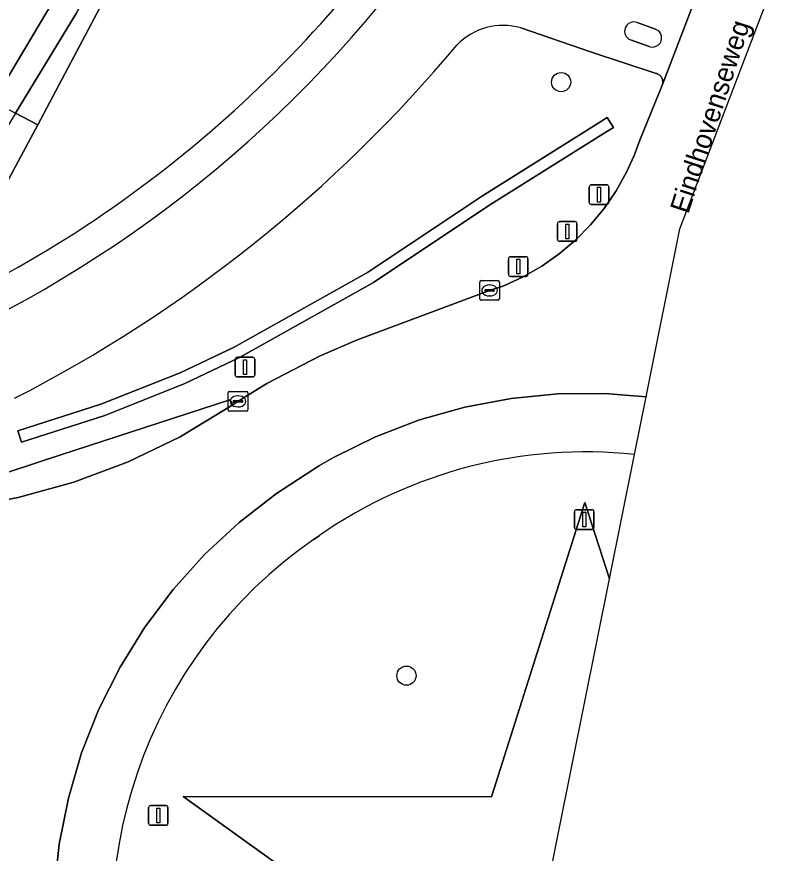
# Model space of a CAD drawing. Extents: x 161385 to 162589, y 388479 to 389756.
# Drawn here: x 162484.61 to 162522.82, y 388644.42 to 388686.96 of the extents above; entities that cross this region are included whole.
import ezdxf

# ---------------------------------------------------------------- set-up
doc = ezdxf.new("R2010")
doc.units = 0
for name, color, linetype in [('IMGEO_Afsluitpaal', 7, 'Continuous'), ('IMGEO_Berm_groen', 7, 'Continuous'), ('IMGEO_Boom', 7, 'Continuous'), ('IMGEO_Fietspad_gesloten', 7, 'Continuous'), ('IMGEO_Groenvoorziening', 7, 'Continuous'), ('IMGEO_Haag', 7, 'Continuous'), ('IMGEO_Kolk', 7, 'Continuous'), ('IMGEO_Lichtmast', 7, 'Continuous'), ('IMGEO_Oever', 7, 'Continuous'), ('IMGEO_Openbare_ruimte_label', 7, 'Continuous'), ('IMGEO_Rijbaan_lokaal_gesloten', 7, 'Continuous'), ('IMGEO_Rijbaan_regionaal_gesloten', 7, 'Continuous'), ('IMGEO_Verkeersbordpaal', 7, 'Continuous'), ('IMGEO_Verkeerseiland_open', 7, 'Continuous'), ('IMGEO_Voetpad_open', 7, 'Continuous'), ('IMGEO_Waterloop', 7, 'Continuous')]:
    doc.layers.add(name, color=color, linetype=linetype)

msp = doc.modelspace()

# ---------------------------------------------------------------- linework, layer by layer
at = {"layer": 'IMGEO_Afsluitpaal'}
for p, q in [((162513.826, 388678.412), (162514.616, 388678.412)), ((162514.616, 388678.412), (162513.826, 388678.412)), ((162513.726, 388677.512), (162513.726, 388678.312)), ((162513.726, 388678.312), (162513.726, 388677.512)), ((162514.716, 388678.312), (162514.716, 388677.512)), ((162514.716, 388677.512), (162514.716, 388678.312)), ((162514.616, 388677.412), (162513.826, 388677.412)), ((162513.826, 388677.412), (162514.616, 388677.412)), ((162512.108, 388675.642), (162512.108, 388676.442)), ((162512.108, 388676.442), (162512.108, 388675.642)), ((162512.208, 388676.542), (162512.998, 388676.542)), ((162512.998, 388676.542), (162512.208, 388676.542)), ((162513.098, 388676.442), (162513.098, 388675.642)), ((162513.098, 388675.642), (162513.098, 388676.442)), ((162512.998, 388675.542), (162512.208, 388675.542)), ((162512.208, 388675.542), (162512.998, 388675.542)), ((162509.615, 388673.854), (162509.615, 388674.654)), ((162509.615, 388674.654), (162509.615, 388673.854)), ((162509.715, 388674.754), (162510.505, 388674.754)), ((162510.505, 388674.754), (162509.715, 388674.754)), ((162510.605, 388674.654), (162510.605, 388673.854)), ((162510.605, 388673.854), (162510.605, 388674.654)), ((162510.505, 388673.754), (162509.715, 388673.754)), ((162509.715, 388673.754), (162510.505, 388673.754))]:
    msp.add_line(p, q, dxfattribs=at)
for points in [[(162514.146, 388678.287), (162514.296, 388678.287), (162514.296, 388677.537), (162514.146, 388677.537), (162514.146, 388678.287)], [(162512.528, 388676.417), (162512.678, 388676.417), (162512.678, 388675.667), (162512.528, 388675.667), (162512.528, 388676.417)], [(162510.035, 388674.629), (162510.185, 388674.629), (162510.185, 388673.879), (162510.035, 388673.879), (162510.035, 388674.629)]]:
    msp.add_lwpolyline(points, dxfattribs=at)
for centre, start, end in [((162513.826, 388678.312), 90, 180), ((162513.826, 388678.312), 90, 180), ((162514.616, 388678.312), 0, 90), ((162514.616, 388678.312), 360, 90), ((162513.826, 388677.512), 180, 270), ((162513.826, 388677.512), 180, 270), ((162514.616, 388677.512), 270, 0), ((162514.616, 388677.512), 270, 0), ((162512.208, 388676.442), 90, 180), ((162512.208, 388676.442), 90, 180), ((162512.998, 388676.442), 0, 90), ((162512.998, 388676.442), 360, 90), ((162512.208, 388675.642), 180, 270), ((162512.208, 388675.642), 180, 270), ((162512.998, 388675.642), 270, 0), ((162512.998, 388675.642), 270, 0), ((162509.715, 388674.654), 90, 180), ((162509.715, 388674.654), 90, 180), ((162510.505, 388674.654), 0, 90), ((162510.505, 388674.654), 360, 90), ((162509.715, 388673.854), 180, 270), ((162509.715, 388673.854), 180, 270), ((162510.505, 388673.854), 270, 0), ((162510.505, 388673.854), 270, 0)]:
    msp.add_arc(centre, 0.1, start, end, dxfattribs=at)
at = {"layer": 'IMGEO_Berm_groen'}
for points in [[(162505.585, 388897.306), (162506.277, 388863.384), (162507.703, 388808.23), (162508.502, 388764.034), (162508.507, 388763.596), (162508.048, 388750), (162507.287, 388742.621), (162504.955, 388729.188), (162504.276, 388726.446), (162500, 388712.436), (162499.893, 388712.133), (162499.135, 388710.054), (162493.393, 388696.514), (162489.638, 388688.939), (162485.689, 388681.463), (162483.678, 388677.768)], [(162508.656, 388673.039), (162509.382, 388673.282), (162510.366, 388673.738), (162511.305, 388674.279), (162512.193, 388674.903), (162513.021, 388675.603), (162513.783, 388676.375), (162514.473, 388677.211), (162515.085, 388678.106), (162515.616, 388679.052), (162515.998, 388679.904), (162516.059, 388680.041), (162516.294, 388680.687), (162517.442, 388683.508), (162517.452, 388683.546), (162517.459, 388683.585), (162517.463, 388683.625), (162517.463, 388683.665), (162517.459, 388683.704), (162517.452, 388683.744), (162517.442, 388683.782), (162517.428, 388683.819), (162517.41, 388683.855), (162517.39, 388683.889), (162517.367, 388683.921), (162517.34, 388683.951), (162517.312, 388683.979), (162517.281, 388684.004), (162517.248, 388684.025), (162517.213, 388684.044), (162517.176, 388684.06), (162517.138, 388684.072), (162517.125, 388684.076), (162513.832, 388685.163), (162510.243, 388686.389)], [(162477.895, 388662.473), (162477.643, 388661.939), (162477.69, 388661.926), (162477.88, 388661.872), (162478.051, 388661.843), (162478.175, 388661.822), (162486.129, 388664.437), (162495.44, 388667.485), (162495.607, 388667.228), (162495.862, 388667.399), (162496.748, 388667.957), (162497.332, 388668.304), (162500, 388669.696), (162501.883, 388670.504), (162508.656, 388673.039)], [(162514.748, 388658.385), (162516.019, 388664.702)], [(162494.427, 388626.225), (162497.722, 388628.282), (162503.834, 388632.097), (162505.832, 388638.132), (162493.072, 388647.301), (162508.754, 388647.299), (162513.5, 388662.259), (162514.748, 388658.385)], [(162500, 388660.582), (162499.73, 388660.392)]]:
    msp.add_lwpolyline(points, dxfattribs=at)
msp.add_lwpolyline([(162508.287, 388677.859), (162514.068, 388681.485), (162514.631, 388681.838), (162514.95, 388681.33), (162514.558, 388681.084), (162508.613, 388677.356), (162502.753, 388673.442), (162495.941, 388669.623), (162493.155, 388668.306), (162489.095, 388666.688), (162484.858, 388665.326), (162484.675, 388665.897), (162488.892, 388667.253), (162492.916, 388668.856), (162495.666, 388670.156), (162502.44, 388673.954)], close=True, dxfattribs=at)
for centre, radius, start, end in [((162454.124, 388727.943), 61.805, 297.52584, 331.17649), ((162509.337, 388683.258), 3.259, 73.8622, 135.6877), ((162451.369, 388732.096), 72.549, 297.17701, 320.07426), ((162513.556, 388641.08), 23.751, 84.0481, 124.8028), ((162513.246, 388640.825), 23.781, 124.6343, 197.578)]:
    msp.add_arc(centre, radius, start, end, dxfattribs=at)
at = {"layer": 'IMGEO_Boom'}
for centre in [(162512.292, 388683.633), (162504.428, 388653.452)]:
    msp.add_circle(centre, 0.489, dxfattribs=at)
at = {"layer": 'IMGEO_Fietspad_gesloten'}
for points in [[(162510.243, 388686.389), (162513.832, 388685.163), (162517.125, 388684.076), (162517.138, 388684.072), (162517.176, 388684.06), (162517.213, 388684.044), (162517.248, 388684.025), (162517.281, 388684.004), (162517.312, 388683.979), (162517.34, 388683.951), (162517.367, 388683.921), (162517.39, 388683.889), (162517.41, 388683.855), (162517.428, 388683.819), (162517.442, 388683.782), (162517.452, 388683.744), (162517.459, 388683.704), (162517.463, 388683.665), (162517.463, 388683.625), (162517.459, 388683.585), (162517.452, 388683.546), (162517.442, 388683.508), (162518.969, 388687.502)], [(162516.158, 388686.664), (162517.09, 388686.319)], [(162516.774, 388685.447), (162515.824, 388685.78)]]:
    msp.add_lwpolyline(points, dxfattribs=at)
for centre, radius, start, end in [((162454.63, 388727.339), 62.661, 297.09439, 328.4075), ((162509.337, 388683.258), 3.259, 73.8622, 135.6877), ((162515.994, 388686.221), 0.473, 69.6865, 248.9176), ((162516.941, 388685.88), 0.464, 248.9204, 71.24), ((162451.369, 388732.096), 72.549, 297.17701, 320.07426)]:
    msp.add_arc(centre, radius, start, end, dxfattribs=at)
at = {"layer": 'IMGEO_Groenvoorziening'}
for points in [[(162508.613, 388677.356), (162514.558, 388681.084), (162514.95, 388681.33), (162514.631, 388681.838), (162514.068, 388681.485), (162508.287, 388677.859), (162502.44, 388673.954), (162495.666, 388670.156), (162492.916, 388668.856), (162488.892, 388667.253), (162484.675, 388665.897), (162484.858, 388665.326), (162489.095, 388666.688), (162493.155, 388668.306), (162495.941, 388669.623), (162502.753, 388673.442)], [(162514.748, 388658.385), (162513.5, 388662.259), (162508.754, 388647.299), (162493.072, 388647.301), (162505.832, 388638.132), (162503.834, 388632.097), (162510.27, 388636.115)]]:
    msp.add_lwpolyline(points, close=True, dxfattribs=at)
at = {"layer": 'IMGEO_Haag'}
msp.add_lwpolyline([(162514.95, 388681.33), (162514.631, 388681.838), (162514.068, 388681.485), (162508.287, 388677.859), (162502.44, 388673.954), (162495.666, 388670.156), (162492.916, 388668.856), (162488.892, 388667.253), (162484.675, 388665.897), (162484.858, 388665.326), (162489.095, 388666.688), (162493.155, 388668.306), (162495.941, 388669.623), (162502.753, 388673.442), (162508.613, 388677.356), (162514.558, 388681.084)], close=True, dxfattribs=at)
at = {"layer": 'IMGEO_Kolk'}
for p, q in [((162508.154, 388672.614), (162508.154, 388673.466)), ((162508.229, 388673.54), (162509.081, 388673.54)), ((162508.642, 388673.32), (162508.667, 388673.32)), ((162509.155, 388673.466), (162509.155, 388672.614)), ((162508.413, 388673.034), (162508.413, 388673.046)), ((162508.851, 388672.997), (162508.453, 388672.997)), ((162508.456, 388673.083), (162508.854, 388673.083)), ((162508.897, 388673.046), (162508.897, 388673.034)), ((162509.081, 388672.54), (162508.229, 388672.54)), ((162508.665, 388672.76), (162508.64, 388672.76)), ((162495.361, 388666.975), (162495.361, 388667.827)), ((162495.436, 388667.901), (162496.288, 388667.901)), ((162496.362, 388667.827), (162496.362, 388666.975)), ((162495.62, 388667.395), (162495.62, 388667.407)), ((162496.058, 388667.358), (162495.66, 388667.358)), ((162495.663, 388667.444), (162496.061, 388667.444)), ((162495.849, 388667.681), (162495.874, 388667.681)), ((162496.104, 388667.407), (162496.104, 388667.395)), ((162495.872, 388667.121), (162495.847, 388667.121)), ((162496.288, 388666.901), (162495.436, 388666.901))]:
    msp.add_line(p, q, dxfattribs=at)
for points in [[(162508.154, 388672.614), (162508.154, 388673.466)], [(162508.229, 388673.54), (162509.081, 388673.54)], [(162509.155, 388673.466), (162509.155, 388672.614)], [(162509.081, 388672.54), (162508.229, 388672.54)], [(162495.361, 388666.975), (162495.361, 388667.827)], [(162495.436, 388667.901), (162496.288, 388667.901)], [(162496.362, 388667.827), (162496.362, 388666.975)], [(162496.288, 388666.901), (162495.436, 388666.901)]]:
    msp.add_lwpolyline(points, dxfattribs=at)
for centre, radius, start, end in [((162508.231, 388673.464), 0.0765, 91.552, 178.448), ((162508.231, 388673.464), 0.0765, 91.552, 178.448), ((162509.079, 388673.464), 0.0765, 1.552, 88.448), ((162509.079, 388673.464), 0.0765, 1.552, 88.448), ((162508.453, 388673.043), 0.0403, 85.8775, 175.7526), ((162508.45, 388673.033), 0.0366, 178.938, 274.7102), ((162508.854, 388673.04), 0.043, 264.8664, 352.4533), ((162508.858, 388673.045), 0.0386, 1.7309, 96.639), ((162508.231, 388672.616), 0.0765, 181.552, 268.448), ((162508.231, 388672.616), 0.0765, 181.552, 268.448), ((162509.079, 388672.616), 0.0765, 271.552, 358.448), ((162509.079, 388672.616), 0.0765, 271.552, 358.448), ((162495.438, 388667.825), 0.0765, 91.552, 178.448), ((162495.438, 388667.825), 0.0765, 91.552, 178.448), ((162496.286, 388667.825), 0.0765, 1.552, 88.448), ((162496.286, 388667.825), 0.0765, 1.552, 88.448), ((162495.66, 388667.404), 0.0403, 85.8775, 175.7526), ((162495.657, 388667.394), 0.0366, 178.938, 274.7102), ((162496.061, 388667.401), 0.043, 264.8664, 352.4533), ((162496.065, 388667.406), 0.0386, 1.7309, 96.639), ((162495.438, 388666.977), 0.0765, 181.552, 268.448), ((162495.438, 388666.977), 0.0765, 181.552, 268.448), ((162496.286, 388666.977), 0.0765, 271.552, 358.448), ((162496.286, 388666.977), 0.0765, 271.552, 358.448)]:
    msp.add_arc(centre, radius, start, end, dxfattribs=at)
for centre, major_axis, ratio, start_param, end_param in [((162508.641, 388673.04), (-0.387, 0.002), 0.722429, 4.712389, 7.853982), ((162508.666, 388673.04), (-0.39, 0.002), 0.717154, 1.570796, 4.712389), ((162495.848, 388667.401), (-0.387, 0.002), 0.722429, 4.712389, 7.853982), ((162495.873, 388667.401), (-0.39, 0.002), 0.717154, 1.570796, 4.712389)]:
    msp.add_ellipse(centre, major_axis=major_axis, ratio=ratio, start_param=start_param, end_param=end_param, dxfattribs=at)
at = {"layer": 'IMGEO_Lichtmast'}
for p, q in [((162495.725, 388668.74), (162495.725, 388669.54)), ((162495.725, 388669.54), (162495.725, 388668.74)), ((162495.825, 388669.64), (162496.615, 388669.64)), ((162496.615, 388669.64), (162495.825, 388669.64)), ((162496.715, 388669.54), (162496.715, 388668.74)), ((162496.715, 388668.74), (162496.715, 388669.54)), ((162496.615, 388668.64), (162495.825, 388668.64)), ((162495.825, 388668.64), (162496.615, 388668.64))]:
    msp.add_line(p, q, dxfattribs=at)
msp.add_lwpolyline([(162496.145, 388669.515), (162496.295, 388669.515), (162496.295, 388668.765), (162496.145, 388668.765), (162496.145, 388669.515)], dxfattribs=at)
for centre, start, end in [((162495.825, 388669.54), 90, 180), ((162495.825, 388669.54), 90, 180), ((162496.615, 388669.54), 0, 90), ((162496.615, 388669.54), 360, 90), ((162495.825, 388668.74), 180, 270), ((162495.825, 388668.74), 180, 270), ((162496.615, 388668.74), 270, 0), ((162496.615, 388668.74), 270, 0)]:
    msp.add_arc(centre, 0.1, start, end, dxfattribs=at)
at = {"layer": 'IMGEO_Oever'}
for points in [[(162505.251, 388735.665), (162504.198, 388730.666), (162501.86, 388721.136), (162498.237, 388710.337), (162494.056, 388699.752), (162487.626, 388687.126), (162484.549, 388682.057), (162485.689, 388681.463), (162489.638, 388688.939), (162493.393, 388696.514), (162499.135, 388710.054), (162499.893, 388712.133), (162500, 388712.436), (162504.276, 388726.446), (162504.955, 388729.188), (162507.287, 388742.621)], [(162501.776, 388732.254), (162500, 388725.157), (162499.917, 388724.855), (162495.354, 388710.803), (162489.554, 388697.215), (162489.547, 388697.2), (162485.912, 388690.204), (162481.666, 388683.56), (162483.406, 388682.653), (162486.57, 388687.943), (162493, 388700.568), (162497.181, 388711.153), (162500.804, 388721.953), (162503.142, 388731.482)], [(162483.678, 388677.768), (162485.689, 388681.463), (162484.549, 388682.057), (162482.834, 388679.23)]]:
    msp.add_lwpolyline(points, dxfattribs=at)
at = {"layer": 'IMGEO_Rijbaan_lokaal_gesloten'}
msp.add_lwpolyline([(162490.272, 388664.327), (162492.917, 388665.605), (162495.437, 388667.114), (162495.607, 388667.228), (162495.44, 388667.485), (162486.129, 388664.437), (162478.175, 388661.822), (162478.879, 388661.703), (162481.804, 388661.973), (162484.693, 388662.504), (162487.523, 388663.291)], close=True, dxfattribs=at)
at = {"layer": 'IMGEO_Rijbaan_regionaal_gesloten'}
for points in [[(162516.609, 388667.637), (162518.325, 388676.171), (162522.824, 388687.961)], [(162518.969, 388687.502), (162517.442, 388683.508), (162516.294, 388680.687), (162516.059, 388680.041), (162515.998, 388679.904), (162515.616, 388679.052), (162515.085, 388678.106), (162514.473, 388677.211), (162513.783, 388676.375), (162513.021, 388675.603), (162512.193, 388674.903), (162511.305, 388674.279), (162510.366, 388673.738), (162509.382, 388673.282), (162508.656, 388673.039), (162501.883, 388670.504), (162500, 388669.696), (162497.332, 388668.304), (162496.748, 388667.957), (162495.862, 388667.399), (162495.607, 388667.228), (162495.437, 388667.114), (162492.917, 388665.605), (162490.272, 388664.327), (162487.523, 388663.291), (162484.693, 388662.504), (162481.804, 388661.973)], [(162486.512, 388642.498), (162486.769, 388644.878), (162487.237, 388647.226), (162487.913, 388649.523), (162488.792, 388651.751), (162489.866, 388653.891), (162491.127, 388655.926), (162492.564, 388657.841), (162494.167, 388659.62), (162495.923, 388661.248), (162497.817, 388662.713), (162500, 388664.142), (162500.713, 388664.546), (162502.861, 388665.599), (162505.095, 388666.455), (162507.397, 388667.109), (162509.747, 388667.554), (162512.128, 388667.787), (162514.521, 388667.807), (162516.609, 388667.637)]]:
    msp.add_lwpolyline(points, dxfattribs=at)
at = {"layer": 'IMGEO_Verkeersbordpaal'}
for p, q in [((162513.072, 388661.889), (162513.862, 388661.889)), ((162513.862, 388661.889), (162513.072, 388661.889)), ((162512.972, 388660.989), (162512.972, 388661.789)), ((162512.972, 388661.789), (162512.972, 388660.989)), ((162513.962, 388661.789), (162513.962, 388660.989)), ((162513.962, 388660.989), (162513.962, 388661.789)), ((162513.862, 388660.889), (162513.072, 388660.889)), ((162513.072, 388660.889), (162513.862, 388660.889)), ((162491.313, 388645.947), (162491.313, 388646.747)), ((162491.313, 388646.747), (162491.313, 388645.947)), ((162491.413, 388646.847), (162492.203, 388646.847)), ((162492.203, 388646.847), (162491.413, 388646.847)), ((162492.303, 388646.747), (162492.303, 388645.947)), ((162492.303, 388645.947), (162492.303, 388646.747)), ((162492.203, 388645.847), (162491.413, 388645.847)), ((162491.413, 388645.847), (162492.203, 388645.847))]:
    msp.add_line(p, q, dxfattribs=at)
for points in [[(162513.392, 388661.764), (162513.542, 388661.764), (162513.542, 388661.014), (162513.392, 388661.014), (162513.392, 388661.764)], [(162491.733, 388646.722), (162491.883, 388646.722), (162491.883, 388645.972), (162491.733, 388645.972), (162491.733, 388646.722)]]:
    msp.add_lwpolyline(points, dxfattribs=at)
for centre, start, end in [((162513.072, 388661.789), 90, 180), ((162513.072, 388661.789), 90, 180), ((162513.862, 388661.789), 0, 90), ((162513.862, 388661.789), 360, 90), ((162513.072, 388660.989), 180, 270), ((162513.072, 388660.989), 180, 270), ((162513.862, 388660.989), 270, 0), ((162513.862, 388660.989), 270, 0), ((162491.413, 388646.747), 90, 180), ((162491.413, 388646.747), 90, 180), ((162492.203, 388646.747), 0, 90), ((162492.203, 388646.747), 360, 90), ((162491.413, 388645.947), 180, 270), ((162491.413, 388645.947), 180, 270), ((162492.203, 388645.947), 270, 0), ((162492.203, 388645.947), 270, 0)]:
    msp.add_arc(centre, 0.1, start, end, dxfattribs=at)
at = {"layer": 'IMGEO_Verkeerseiland_open'}
for points in [[(162517.09, 388686.319), (162516.158, 388686.664)], [(162515.824, 388685.78), (162516.774, 388685.447)], [(162516.019, 388664.702), (162516.609, 388667.637), (162514.521, 388667.807), (162512.128, 388667.787), (162509.747, 388667.554), (162507.397, 388667.109), (162505.095, 388666.455), (162502.861, 388665.599), (162500.713, 388664.546), (162500, 388664.142), (162497.817, 388662.713), (162495.923, 388661.248), (162494.167, 388659.62), (162492.564, 388657.841), (162491.127, 388655.926), (162489.866, 388653.891), (162488.792, 388651.751), (162487.913, 388649.523), (162487.237, 388647.226), (162486.769, 388644.878), (162486.512, 388642.498)], [(162499.73, 388660.392), (162500, 388660.582)]]:
    msp.add_lwpolyline(points, dxfattribs=at)
for centre, radius, start, end in [((162515.994, 388686.221), 0.473, 69.6865, 248.9176), ((162516.941, 388685.88), 0.464, 248.9204, 71.24), ((162513.556, 388641.08), 23.751, 84.0481, 124.8028), ((162513.246, 388640.825), 23.781, 124.6343, 197.578)]:
    msp.add_arc(centre, radius, start, end, dxfattribs=at)
at = {"layer": 'IMGEO_Voetpad_open'}
for centre, radius, start, end in [((162454.124, 388727.943), 61.805, 297.52584, 331.17649), ((162454.63, 388727.339), 62.661, 297.09439, 328.4075)]:
    msp.add_arc(centre, radius, start, end, dxfattribs=at)
at = {"layer": 'IMGEO_Waterloop'}
msp.add_lwpolyline([(162503.142, 388731.482), (162500.804, 388721.953), (162497.181, 388711.153), (162493, 388700.568), (162486.57, 388687.943), (162483.406, 388682.653), (162484.549, 388682.057), (162487.626, 388687.126), (162494.056, 388699.752), (162498.237, 388710.337), (162501.86, 388721.136), (162504.198, 388730.666), (162505.251, 388735.665)], dxfattribs=at)

# ---------------------------------------------------------------- texts
at = {"layer": 'IMGEO_Openbare_ruimte_label'}
msp.add_text('Eindhovenseweg', height=1, rotation=71.9454, dxfattribs=at).set_placement((162518.756, 388676.894))

doc.saveas('drawing.dxf')
